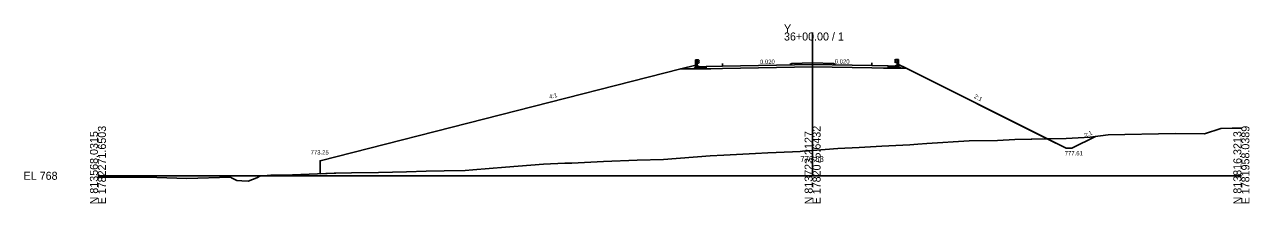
# Model space of a CAD drawing. Extents: x -12583 to 5303, y -44 to 25667.
# Drawn here: x 1874.3 to 2302.8, y 6490.3 to 6552.9 of the extents above; entities that cross this region are included whole.
import ezdxf

# ---------------------------------------------------------------- set-up
doc = ezdxf.new("R2010")
doc.units = 0
for name, color, linetype in [('Exist Cross Section Cell', 7, 'Continuous'), ('Exist XS Center Line Elevation Label', 7, 'Continuous'), ('Exist XS Ground Line', 7, 'Continuous'), ('Prop Conc 5in Monolithic Surface Mount Island', 7, 'Continuous'), ('Prop XS Ditch Standard Text', 7, 'Continuous'), ('Prop XS Dump Level', 7, 'Continuous'), ('Prop XS Earthwork Shape', 7, 'Continuous'), ('Prop XS EOT Tick Mark', 7, 'Continuous'), ('Prop XS Finish Grade', 7, 'Continuous'), ('Prop XS Finish Grade CurbGutter', 7, 'Continuous'), ('Prop XS Finish Grade Earthwork', 7, 'Continuous'), ('Prop XS Finish Grade Paved Shoulder', 7, 'Continuous'), ('Prop XS Finish Grade Pavement', 7, 'Continuous'), ('Prop XS Guardrail', 7, 'Continuous'), ('Prop XS Pvmt Edge Slope', 7, 'Continuous'), ('Prop XS SE Text', 7, 'Continuous'), ('Prop XS Side Slope Text', 7, 'Continuous'), ('Prop XS Subgrade CurbGutter', 7, 'Continuous'), ('Prop XS Subgrade Earthwork', 7, 'Continuous')]:
    doc.layers.add(name, color=color, linetype=linetype)

msp = doc.modelspace()

# ---------------------------------------------------------------- linework, layer by layer
at = {"layer": 'Exist Cross Section Cell'}
for p, q in [((2150, 6500), (2150, 6550.12)), ((1900, 6500), (2150, 6500)), ((2150, 6500), (2300, 6500))]:
    msp.add_line(p, q, dxfattribs=at)
at = {"layer": 'Exist XS Ground Line'}
for p, q in [((2247.09, 6513.52), (2253.43, 6514.28)), ((2253.43, 6514.28), (2276.86, 6514.79)), ((2276.86, 6514.79), (2287.12, 6514.7)), ((2287.12, 6514.7), (2292.82, 6516.57)), ((2292.82, 6516.57), (2296.81, 6516.71)), ((2296.81, 6516.71), (2300, 6516.69)), ((2150, 6508.88), (2158.82, 6509.5)), ((2158.82, 6509.5), (2166.26, 6509.88)), ((2166.26, 6509.88), (2174.21, 6510.37)), ((2174.21, 6510.37), (2184, 6510.83)), ((2184, 6510.83), (2186.83, 6511.01)), ((2186.83, 6511.01), (2190.01, 6511.25)), ((2190.01, 6511.25), (2204.72, 6512.22)), ((2204.72, 6512.22), (2214.63, 6512.35)), ((2214.63, 6512.35), (2220.72, 6512.65)), ((2220.72, 6512.65), (2238.74, 6513.07)), ((2238.74, 6513.07), (2247.09, 6513.52)), ((2076.86, 6504.97), (2088.6, 6505.51)), ((2088.6, 6505.51), (2097.84, 6505.68)), ((2097.84, 6505.68), (2114.14, 6506.99)), ((2114.14, 6506.99), (2118.97, 6507.22)), ((2118.97, 6507.22), (2129.97, 6507.74)), ((2129.97, 6507.74), (2134.33, 6508.05)), ((2134.33, 6508.05), (2142.99, 6508.43)), ((2142.99, 6508.43), (2145.68, 6508.54)), ((2145.68, 6508.54), (2146.44, 6508.64)), ((2146.44, 6508.64), (2150, 6508.88)), ((1968.04, 6500.37), (1982.64, 6500.87)), ((1982.64, 6500.87), (1983.25, 6500.92)), ((1983.25, 6500.92), (1988.65, 6501.03)), ((1988.65, 6501.03), (1998.15, 6501.1)), ((1998.15, 6501.1), (2007.96, 6501.38)), ((2007.96, 6501.38), (2014.81, 6501.6)), ((2014.81, 6501.6), (2021.17, 6501.75)), ((2021.17, 6501.75), (2028.51, 6501.87)), ((2028.51, 6501.87), (2031.14, 6502.08)), ((2031.14, 6502.08), (2042.55, 6502.97)), ((2042.55, 6502.97), (2055.92, 6504.12)), ((2055.92, 6504.12), (2063.36, 6504.36)), ((2063.36, 6504.36), (2065.76, 6504.42)), ((2065.76, 6504.42), (2067.99, 6504.55)), ((2067.99, 6504.55), (2076.86, 6504.97)), ((1900, 6499.37), (1917.07, 6499.49)), ((1917.07, 6499.49), (1931.09, 6499.1)), ((1931.09, 6499.1), (1946.36, 6499.52)), ((1946.36, 6499.52), (1946.68, 6499.34)), ((1946.68, 6499.34), (1948.54, 6498.32)), ((1948.54, 6498.32), (1950.33, 6498.27)), ((1950.33, 6498.27), (1952.58, 6498.08)), ((1952.58, 6498.08), (1955.55, 6499.31)), ((1955.55, 6499.31), (1956.67, 6499.81)), ((1956.67, 6499.81), (1957.79, 6499.93)), ((1957.79, 6499.93), (1960.43, 6500.18)), ((1960.43, 6500.18), (1968.04, 6500.37))]:
    msp.add_line(p, q, dxfattribs=at)
at = {"layer": 'Prop Conc 5in Monolithic Surface Mount Island'}
for p, q in [((2142.74, 6539.22), (2150, 6539.51)), ((2157.26, 6539.22), (2150, 6539.51)), ((2142, 6538.95), (2142.74, 6539.22)), ((2142, 6538.79), (2142, 6538.95)), ((2158, 6538.95), (2157.26, 6539.22)), ((2158, 6538.79), (2158, 6538.95))]:
    msp.add_line(p, q, dxfattribs=at)
at = {"layer": 'Prop XS Dump Level'}
for p, q in [((2118.45, 6538.32), (2150, 6538.95)), ((2150, 6538.95), (2170.75, 6538.53))]:
    msp.add_line(p, q, dxfattribs=at)
at = {"layer": 'Prop XS Earthwork Shape'}
for points in [[(2112.74, 6537.41), (2108.29, 6537.41), (2103.89, 6537.41), (1977.73, 6505.25), (1977.73, 6500.7), (1982.64, 6500.87), (1983.25, 6500.92), (1988.65, 6501.03), (1998.15, 6501.1), (2007.96, 6501.38), (2014.81, 6501.6), (2021.17, 6501.75), (2028.51, 6501.87), (2031.14, 6502.08), (2042.55, 6502.97), (2055.92, 6504.12), (2063.36, 6504.36), (2065.76, 6504.42), (2067.99, 6504.55), (2076.86, 6504.97), (2088.6, 6505.51), (2097.84, 6505.68), (2114.14, 6506.99), (2118.97, 6507.22), (2129.97, 6507.74), (2134.33, 6508.05), (2142.99, 6508.43), (2145.68, 6508.54), (2146.44, 6508.64), (2150, 6508.88), (2158.82, 6509.5), (2166.26, 6509.88), (2174.21, 6510.37), (2184, 6510.83), (2186.83, 6511.01), (2190.01, 6511.25), (2204.72, 6512.22), (2214.63, 6512.35), (2220.72, 6512.65), (2232.1, 6512.92), (2182.68, 6537.62), (2180.81, 6537.62), (2176.42, 6537.63), (2174.75, 6537.66), (2170.75, 6537.74), (2150, 6538.16), (2118.45, 6537.53), (2114.45, 6537.45)], [(2247.09, 6513.52), (2248.98, 6513.74), (2240.71, 6509.61), (2238.71, 6509.61), (2232.1, 6512.92), (2238.74, 6513.07)]]:
    msp.add_lwpolyline(points, close=True, dxfattribs=at)
at = {"layer": 'Prop XS EOT Tick Mark'}
for p, q in [((2170.75, 6538.53), (2170.75, 6539.53)), ((2118.45, 6538.32), (2118.45, 6539.32))]:
    msp.add_line(p, q, dxfattribs=at)
at = {"layer": 'Prop XS Finish Grade'}
for p, q in [((2109.11, 6538.74), (2103.89, 6537.41)), ((2109.7, 6538.45), (2109.11, 6538.74)), ((2179.44, 6538.67), (2180.02, 6538.96)), ((2182.68, 6537.62), (2180.02, 6538.96))]:
    msp.add_line(p, q, dxfattribs=at)
at = {"layer": 'Prop XS Finish Grade CurbGutter'}
for p, q in [((2110.4, 6538.11), (2109.7, 6538.45)), ((2112.74, 6538.2), (2110.4, 6538.11)), ((2176.42, 6538.42), (2178.75, 6538.33)), ((2178.75, 6538.33), (2179.44, 6538.67))]:
    msp.add_line(p, q, dxfattribs=at)
at = {"layer": 'Prop XS Finish Grade Earthwork'}
for p, q in [((2103.89, 6537.41), (1977.73, 6505.25)), ((2182.68, 6537.62), (2238.71, 6509.61)), ((2248.98, 6513.74), (2240.71, 6509.61)), ((2238.71, 6509.61), (2240.71, 6509.61)), ((1977.73, 6500.7), (1977.73, 6505.25))]:
    msp.add_line(p, q, dxfattribs=at)
at = {"layer": 'Prop XS Finish Grade Paved Shoulder'}
for p, q in [((2118.45, 6538.32), (2112.74, 6538.2)), ((2170.75, 6538.53), (2176.42, 6538.42))]:
    msp.add_line(p, q, dxfattribs=at)
at = {"layer": 'Prop XS Finish Grade Pavement'}
for p, q in [((2118.45, 6538.32), (2150, 6538.95)), ((2150, 6538.95), (2170.75, 6538.53))]:
    msp.add_line(p, q, dxfattribs=at)
at = {"layer": 'Prop XS Guardrail'}
for p, q in [((2109.07, 6538), (2109.07, 6540.5)), ((2109.07, 6540.5), (2109.57, 6540.5)), ((2109.57, 6540.5), (2109.57, 6538)), ((2109.57, 6540.5), (2110.07, 6540.5)), ((2110.07, 6540.5), (2110.37, 6540.3)), ((2110.37, 6540.18), (2110.07, 6539.98)), ((2110.07, 6539.98), (2110.07, 6539.89)), ((2110.07, 6539.89), (2110.37, 6539.69)), ((2110.37, 6539.57), (2110.07, 6539.37)), ((2110.37, 6540.3), (2110.4, 6540.24)), ((2110.4, 6540.24), (2110.37, 6540.18)), ((2110.37, 6539.69), (2110.4, 6539.63)), ((2110.4, 6539.63), (2110.37, 6539.57)), ((2178.78, 6540.52), (2178.75, 6540.46)), ((2178.75, 6540.46), (2178.78, 6540.4)), ((2178.78, 6539.91), (2178.75, 6539.85)), ((2178.75, 6539.85), (2178.78, 6539.79)), ((2179.07, 6540.72), (2178.78, 6540.52)), ((2178.78, 6540.4), (2179.07, 6540.2)), ((2179.07, 6540.11), (2178.78, 6539.91)), ((2178.78, 6539.79), (2179.07, 6539.59)), ((2179.57, 6540.72), (2179.07, 6540.72)), ((2179.07, 6540.2), (2179.07, 6540.11)), ((2179.07, 6539.59), (2179.57, 6539.59)), ((2180.07, 6540.72), (2179.57, 6540.72)), ((2179.57, 6540.72), (2179.57, 6538.22)), ((2180.07, 6538.22), (2180.07, 6540.72)), ((2110.07, 6539.37), (2109.57, 6539.37))]:
    msp.add_line(p, q, dxfattribs=at)
at = {"layer": 'Prop XS Pvmt Edge Slope'}
for p, q in [((2108.69, 6537.78), (2108.29, 6537.41)), ((2109.7, 6537.78), (2108.69, 6537.78)), ((2179.44, 6538), (2180.44, 6538)), ((2180.44, 6538), (2180.81, 6537.62))]:
    msp.add_line(p, q, dxfattribs=at)
at = {"layer": 'Prop XS Subgrade CurbGutter'}
for p, q in [((2109.7, 6537.78), (2109.7, 6538.45)), ((2112.74, 6537.78), (2109.7, 6537.78)), ((2112.74, 6538.2), (2112.74, 6537.78)), ((2176.42, 6538.42), (2176.42, 6538)), ((2176.42, 6538), (2179.44, 6538)), ((2179.44, 6538), (2179.44, 6538.67))]:
    msp.add_line(p, q, dxfattribs=at)
at = {"layer": 'Prop XS Subgrade Earthwork'}
for p, q in [((2108.29, 6537.41), (2103.89, 6537.41)), ((2112.74, 6537.41), (2108.29, 6537.41)), ((2114.45, 6537.45), (2112.74, 6537.41)), ((2118.45, 6537.53), (2114.45, 6537.45)), ((2150, 6538.16), (2118.45, 6537.53)), ((2170.75, 6537.74), (2150, 6538.16)), ((2170.75, 6537.74), (2174.75, 6537.66)), ((2174.75, 6537.66), (2176.42, 6537.63)), ((2176.42, 6537.63), (2176.42, 6537.62)), ((2176.42, 6537.62), (2180.81, 6537.62)), ((2180.81, 6537.62), (2182.68, 6537.62))]:
    msp.add_line(p, q, dxfattribs=at)

# ---------------------------------------------------------------- texts
at = {"layer": 'Exist Cross Section Cell'}
for s, p in [('Y', (2140, 6550.12)), ('36+00.00 / 1', (2140, 6547.32)), ('EL 768', (1874, 6498.6))]:
    msp.add_text(s, height=2.8, dxfattribs=at).set_placement(p)
for s, p in [('N 813568.0315', (1900, 6490)), ('E 1782271.6503', (1902.8, 6490)), ('N 813723.2127', (2150, 6490)), ('E 1782075.6432', (2152.8, 6490)), ('N 813816.3213', (2300, 6490)), ('E 1781958.0389', (2302.8, 6490))]:
    msp.add_text(s, height=2.8, rotation=90, dxfattribs=at).set_placement(p)
at = {"layer": 'Exist XS Center Line Elevation Label'}
msp.add_text('776.88', height=2, dxfattribs=at).set_placement((2145.73, 6504.88))
at = {"layer": 'Prop XS Ditch Standard Text'}
for s, p in [('773.25', (1974.41, 6507.45)), ('777.61', (2238.2, 6507.12))]:
    msp.add_text(s, height=1.5, dxfattribs=at).set_placement(p)
at = {"layer": 'Prop XS Dump Level'}
msp.add_text('Case2', height=0.04, dxfattribs=at).set_placement((2176.42, 6538.38))
at = {"layer": 'Prop XS SE Text'}
for rotation, p in [(1.1458, (2131.6, 6539.08)), (358.8542, (2157.75, 6539.29))]:
    msp.add_text('0.020', height=1.5, rotation=rotation, dxfattribs=at).set_placement(p)
at = {"layer": 'Prop XS Side Slope Text'}
for s, rotation, p in [('4:1', 15.3505, (2058.06, 6526.85)), ('2:1', 333.4349, (2206.32, 6527.28)), ('2:1', 26.5651, (2245.46, 6513.32))]:
    msp.add_text(s, height=1.5, rotation=rotation, dxfattribs=at).set_placement(p)

doc.saveas('drawing.dxf')
